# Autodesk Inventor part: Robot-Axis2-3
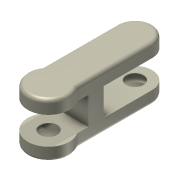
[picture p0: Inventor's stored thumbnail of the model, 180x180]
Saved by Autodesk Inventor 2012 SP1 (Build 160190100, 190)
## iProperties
Shininess: 21.0
Length Units: 11269
Angle Units: 11279
Time Units: 11290
Mass Units: 11283
Length Display Precision: 3
Angle Display Precision: 2
Created: 2001-08
Part Number: Robot-Axis2-3
Document SubType Name: ﾓﾃﾞﾘﾝｸﾞ
Designer: Administrator
Density: 1 g/cm^3
Material: Default
Density: 0.0
Volumn: 0.0
Area: 0.0
PropertySet Name: Model Information
Control State: 0
Master: False
Checked Out: False
Author: Administrator
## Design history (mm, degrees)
node "作業平面1"
sketch "ｽｹｯﾁ2"
  geometry: L1 (0, 0)-(0, 250); L2 (0, 250)-(-50, 250); L3 (-50, 250)-(-50, 33.166); L4 (0, 250)-(50, 250); L5 (50, 250)-(50, 33.166); A1 r 60 centre (0, 0) between (-50, 33.166) and (50, 33.166); A2 r 50 centre (0, 250) between (-50, 250) and (50, 250)
  constraints: 10 end point, 4 point on circle, 2 centre point, 2 perpendicular, 2 tangent, 1 coincident, 1 vertical, 1 other
  dimensions: "d1" = 120 diameter of A1; "d2" = 250 distance of L1.start L1.end; "d3" = 100 diameter of A2
extrude "押し出し1" new body sketch "ｽｹｯﾁ2" distance "d4" = 38; taper "d5" = 0 deg
sketch "ｽｹｯﾁ3"
  geometry: L1 (-50, 250)-(-50, 33.166) reference; L2 (50, 33.166)-(50, 250) reference; L3 (-50, 65)-(50, 65); L4 (50, 65)-(50, 110); L5 (50, 110)-(-50, 110); L6 (-50, 110)-(-50, 65); C1 r 60 at (0, 0); A1 r 60 centre (0, 0) between (-50, 33.166) and (50, 33.166) reference
  constraints: 8 end point, 2 parallel, 2 point on line, 1 centre point, 1 coincident, 1 concentric, 1 horizontal, 1 perpendicular
  dimensions: "d7" = 65 distance from line of L3 C1.centre; "d8" = 140 distance from line of L5 L1.start
extrude "押し出し2" join sketch "ｽｹｯﾁ3" stored distance "d9" = 10; taper "d10" = 0 deg
shell "Shell1" dims "d11" = 2
sketch "Sketch4"
  geometry: A1 r 60 centre (0, 0) between (-50, 33.166) and (50, 33.166) reference
hole "Hole1" sketch "Sketch4" at (0, 0) diameter "d12" = 50; stored, may be unused: countersink angle "d16" = 82 deg, drill point angle "d18" = 118 deg; dims "d13" = 6, "d14" = 4, "d15" = 2, "d17" = 2
sketch "Sketch5"
  geometry: A1 r 60 centre (0, 0) between (-50, 33.166) and (50, 33.166) reference
hole "Hole2" sketch "Sketch5" at (0, 0) diameter "d19" = 50; stored, may be unused: countersink angle "d23" = 82 deg, drill point angle "d25" = 118 deg; dims "d20" = 6, "d21" = 4, "d22" = 2, "d24" = 2
sketch "Sketch6"
  geometry: A1 r 50 centre (0, 250) between (50, 250) and (-50, 250) reference
hole "Hole3" sketch "Sketch6" at (0, 250) diameter "d26" = 50; stored, may be unused: countersink angle "d30" = 82 deg, drill point angle "d32" = 118 deg; dims "d27" = 6, "d28" = 4, "d29" = 2, "d31" = 2
sketch "Sketch7"
  geometry: A1 r 50 centre (0, 0) between (50, 0) and (-50, 0) reference
hole "Hole4" sketch "Sketch7" at (0, 0) diameter "d33" = 50; stored, may be unused: countersink angle "d37" = 82 deg, drill point angle "d39" = 118 deg; dims "d34" = 6, "d35" = 4, "d36" = 2, "d38" = 2
body "Solid1"
fillet "Fillet" dims "d6" = 10
mirror "Mirror"
